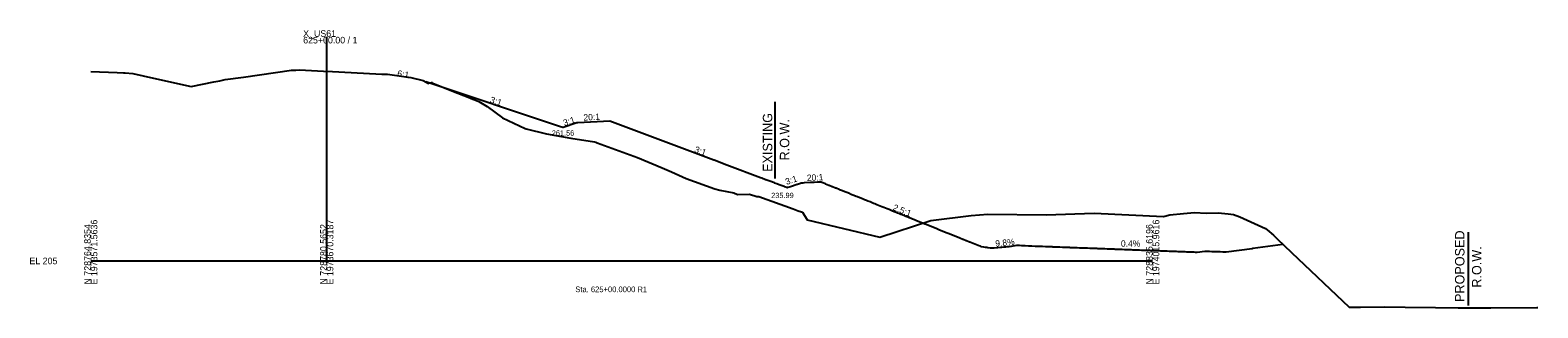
# Model space of a CAD drawing. Extents: x -26 to 630, y -39 to 9098.
# Drawn here: x -26 to 613, y 2480 to 2598 of the extents above; entities that cross this region are included whole.
import ezdxf

# ---------------------------------------------------------------- set-up
doc = ezdxf.new("R2010")
doc.units = 0
for name, color, linetype in [('CONST_DCH', 7, 'Continuous'), ('Default', 7, 'Continuous'), ('Draft_XS_Grid', 7, 'Continuous'), ('Draft_XS_Text', 7, 'Continuous'), ('DTM CONTOURS_MAJOR', 7, 'Continuous'), ('DTM_X_GROUND', 7, 'Continuous'), ('X_DTM_CONTOURS_MAJOR', 7, 'Continuous'), ('XS_CELL', 7, 'Continuous'), ('XS_P_GROUND', 7, 'Continuous'), ('XS_P_ROW', 7, 'Continuous'), ('XS_P_TX_DCH', 7, 'Continuous'), ('XS_P_TX_FS_BS', 7, 'Continuous'), ('XS_X_ROW', 7, 'Continuous')]:
    doc.layers.add(name, color=color, linetype=linetype)

msp = doc.modelspace()

# ---------------------------------------------------------------- linework, layer by layer
at = {"layer": 'DTM_X_GROUND'}
msp.add_lwpolyline([(0, 2580.3), (11.19, 2579.9), (13.9, 2579.81), (14.57, 2579.76), (17.78, 2579.5), (26.51, 2577.53), (42.52, 2573.93), (52.18, 2575.92), (54.64, 2576.42), (56.93, 2576.9), (64.73, 2577.95), (85.12, 2580.85), (86.96, 2580.91), (88.47, 2580.96), (98.67, 2580.48), (102.39, 2580.31), (120.83, 2579.29), (123.37, 2579.15), (123.68, 2579.15), (125.72, 2579.15), (135.68, 2577.7), (140.89, 2576.56), (143.07, 2575.21), (143.58, 2575.49), (144.39, 2575.7), (144.61, 2575.62), (144.93, 2575.39), (145.72, 2575.05), (153.72, 2571.82), (158.12, 2570.1), (159.89, 2569.41), (161.92, 2568.62), (162.07, 2568.56), (164.42, 2567.52), (167.94, 2565.51), (174.48, 2560.69), (184.09, 2556.1), (184.45, 2555.96), (193.07, 2553.95), (203.5, 2552.1), (213.51, 2550.53), (214.08, 2550.34), (214.59, 2550.13), (231.73, 2543.82), (242.14, 2539.43), (246.11, 2537.81), (252.29, 2534.95), (264.47, 2530.56), (266.54, 2530), (272.46, 2528.82), (274.03, 2528.18), (279.09, 2528.33), (282.28, 2527.36), (282.33, 2527.36), (282.49, 2527.33), (282.66, 2527.31), (283.11, 2527.25), (297.66, 2522.07), (299.83, 2521.3), (301.22, 2520.81), (301.6, 2520.68), (303.55, 2517.41), (334.34, 2510.01), (355.93, 2517.07), (373.03, 2519.2), (380.1, 2519.82), (404.84, 2519.51), (425.28, 2520.24), (454.58, 2518.87), (457.31, 2519.61), (463.03, 2520.17), (467.75, 2520.46), (472.69, 2520.2), (477.83, 2520.32), (481.97, 2519.94), (484.21, 2519.67), (486.9, 2518.73), (497.76, 2513.69), (498.58, 2513.16), (501.24, 2510.99), (502.78, 2509.41), (508.86, 2503.62), (533.24, 2480.42), (538.12, 2480.42), (548.11, 2480.5), (557.01, 2480.4), (569.85, 2480.26), (579.4, 2480.15), (593.33, 2480.1), (612.75, 2480.22), (613.23, 2480.19)], dxfattribs=at)
at = {"layer": 'XS_CELL'}
for p, q in [((100, 2500), (100, 2595)), ((0, 2500), (100, 2500)), ((100, 2500), (450, 2500))]:
    msp.add_line(p, q, dxfattribs=at)
at = {"layer": 'XS_P_GROUND'}
for points in [[(309.68, 2533.42), (308.78, 2533.38), (308.07, 2533.34), (308, 2533.34), (306.61, 2533.27), (306.56, 2533.26), (305.14, 2533.19), (305.07, 2533.19), (302.36, 2533.05), (302.32, 2533.05), (301.75, 2533.02), (301.15, 2532.99), (300.92, 2532.91), (300.78, 2532.87), (299.47, 2532.43), (299.36, 2532.4), (296.56, 2531.46), (296.52, 2531.45), (295.41, 2531.08), (295.15, 2530.99), (295.11, 2531.01), (294.96, 2531.07), (293.96, 2531.44), (293.85, 2531.49), (291.77, 2532.27), (291.73, 2532.28), (290.73, 2532.66), (290.7, 2532.67), (289.73, 2533.03), (289.68, 2533.05), (287.82, 2533.75), (287.8, 2533.76), (286.92, 2534.09), (286.89, 2534.1), (286.04, 2534.42), (285.99, 2534.44), (284.36, 2535.05), (283.77, 2535.27), (269.48, 2540.65), (264.13, 2542.66), (263.99, 2542.72), (221.04, 2558.87), (220, 2559.26), (206.35, 2558.58), (206, 2558.56), (200.15, 2556.61), (200, 2556.56), (198.57, 2557.03), (142, 2575.89)], [(309.68, 2533.42), (309.84, 2533.36), (309.84, 2533.36), (311.29, 2532.77), (311.35, 2532.75), (312.75, 2532.18), (312.85, 2532.14), (314.21, 2531.6), (314.36, 2531.53), (315.66, 2531.01), (315.86, 2530.93), (317.12, 2530.42), (317.36, 2530.32), (318.57, 2529.83), (318.86, 2529.72), (320.03, 2529.25), (320.36, 2529.11), (321.48, 2528.66), (321.86, 2528.51), (322.94, 2528.07), (323.35, 2527.9), (324.4, 2527.48), (324.85, 2527.3), (325.85, 2526.9), (326.34, 2526.7), (327.31, 2526.31), (327.84, 2526.1), (328.76, 2525.72), (329.33, 2525.49), (330.22, 2525.14), (330.82, 2524.89), (331.67, 2524.55), (332.32, 2524.29), (333.13, 2523.96), (333.81, 2523.69), (334.59, 2523.37), (335.3, 2523.09), (336.04, 2522.79), (336.79, 2522.49), (337.5, 2522.2), (338.27, 2521.88), (338.95, 2521.61), (339.76, 2521.28), (340.41, 2521.02), (341.25, 2520.68), (341.86, 2520.44), (342.45, 2520.2), (343.32, 2519.85), (343.89, 2519.62), (344.77, 2519.26), (345.33, 2519.04), (346.23, 2518.67), (346.77, 2518.46), (347.69, 2518.09), (348.21, 2517.87), (349.14, 2517.5), (349.65, 2517.29), (350.6, 2516.91), (351.09, 2516.71), (352.05, 2516.33), (352.53, 2516.13), (353.51, 2515.74), (353.96, 2515.56), (354.96, 2515.15), (355.4, 2514.98), (356.42, 2514.56), (356.83, 2514.4), (357.88, 2513.98), (358.27, 2513.82), (359.33, 2513.39), (359.7, 2513.24), (360.79, 2512.8), (361.13, 2512.66), (362.24, 2512.21), (362.56, 2512.08), (363.7, 2511.63), (363.99, 2511.51), (365.15, 2511.04), (365.42, 2510.93), (366.61, 2510.45), (366.85, 2510.35), (368.07, 2509.86), (368.28, 2509.78), (369.52, 2509.28), (369.7, 2509.2), (370.98, 2508.69), (371.13, 2508.63), (372.43, 2508.1), (372.55, 2508.05), (373.89, 2507.52), (373.97, 2507.48), (375.34, 2506.93), (375.39, 2506.91), (376.8, 2506.34), (376.81, 2506.34), (377.21, 2506.17), (378.26, 2506.01), (379.06, 2505.88), (379.71, 2505.77), (380.14, 2505.7), (381.17, 2505.54), (381.34, 2505.51)], [(381.34, 2505.51), (382.62, 2505.61), (382.79, 2505.62), (384.08, 2505.73), (384.44, 2505.76), (385.53, 2505.85), (386.09, 2505.89), (386.99, 2505.96), (387.74, 2506.03), (388.45, 2506.08), (388.9, 2506.12), (389.18, 2506.14), (389.99, 2506.26), (390.24, 2506.29), (392.4, 2506.62), (392.58, 2506.64), (393.11, 2506.72), (393.15, 2506.73), (393.16, 2506.73), (393.56, 2506.7), (394.42, 2506.53), (394.44, 2506.53), (395.87, 2506.48), (395.91, 2506.48), (397.32, 2506.42), (397.38, 2506.42), (398.76, 2506.37), (398.85, 2506.37), (400.21, 2506.32), (400.32, 2506.31), (401.65, 2506.26), (401.79, 2506.26), (403.1, 2506.21), (403.26, 2506.2), (404.55, 2506.15), (404.74, 2506.15), (405.99, 2506.1), (406.21, 2506.09), (407.44, 2506.05), (407.68, 2506.04), (408.89, 2505.99), (409.15, 2505.98), (410.34, 2505.94), (410.62, 2505.93), (411.79, 2505.88), (412.09, 2505.87), (413.24, 2505.83), (413.56, 2505.82), (414.7, 2505.77), (415.03, 2505.76), (416.15, 2505.72), (416.5, 2505.71), (417.61, 2505.67), (417.97, 2505.65), (419.06, 2505.61), (419.44, 2505.6), (420.52, 2505.56), (420.91, 2505.54), (421.97, 2505.5), (422.39, 2505.49), (423.43, 2505.45), (423.86, 2505.43), (424.89, 2505.39), (425.33, 2505.38), (426.34, 2505.34), (426.8, 2505.32), (427.8, 2505.28), (428.27, 2505.27), (429.26, 2505.23), (429.74, 2505.21), (430.72, 2505.18), (431.21, 2505.16), (432.18, 2505.12), (432.68, 2505.1), (433.64, 2505.07), (434.15, 2505.05), (435.1, 2505.01), (435.62, 2504.99), (436.56, 2504.96), (437.09, 2504.94), (438.02, 2504.9), (438.56, 2504.88), (439.48, 2504.85), (440.04, 2504.83), (440.96, 2504.79), (441.51, 2504.77), (442.42, 2504.74), (442.98, 2504.72), (443.87, 2504.68), (444.45, 2504.66), (445.33, 2504.63), (445.92, 2504.61), (446.52, 2504.59), (447.39, 2504.55), (448.01, 2504.53), (448.86, 2504.5), (449.5, 2504.47), (450.33, 2504.44), (450.99, 2504.42), (451.8, 2504.39), (452.48, 2504.36), (453.27, 2504.33), (453.97, 2504.31), (454.74, 2504.28), (455.46, 2504.25), (456.21, 2504.22), (456.94, 2504.2), (457.68, 2504.17), (458.43, 2504.14), (459.16, 2504.11), (459.92, 2504.08), (460.63, 2504.06), (461.42, 2504.03), (462.1, 2504), (462.91, 2503.97), (463.57, 2503.95), (464.4, 2503.92), (465.04, 2503.89), (465.89, 2503.86), (466.51, 2503.84), (467.38, 2503.81), (467.98, 2503.78), (468.51, 2503.76), (468.86, 2503.75), (472.15, 2504.1), (472.57, 2504.12), (473.56, 2504.09), (474.09, 2504.07), (475.1, 2504.04), (475.61, 2504.03), (476.64, 2504), (477.13, 2503.99), (478.19, 2503.96), (478.65, 2503.94), (479.73, 2503.91), (480.17, 2503.9), (480.85, 2503.88), (481.12, 2503.87), (492.15, 2505.31), (492.43, 2505.35), (505.14, 2507.11)]]:
    msp.add_lwpolyline(points, dxfattribs=at)
at = {"layer": 'XS_P_ROW'}
msp.add_line((583.73, 2512.13), (583.73, 2481.12), dxfattribs=at)
at = {"layer": 'XS_X_ROW'}
msp.add_line((290, 2535), (290, 2567.48), dxfattribs=at)

# ---------------------------------------------------------------- texts
at = {"layer": 'CONST_DCH'}
msp.add_text('X', height=0.001, dxfattribs=at).set_placement((393.56, 2506.7))
at = {"layer": 'Default'}
for p in [(199.96, 2556.5), (199.96, 2556.5), (295.12, 2530.93), (356.5, 2517.08)]:
    msp.add_text('X', height=0.12, dxfattribs=at).set_placement(p)
at = {"layer": 'Draft_XS_Grid'}
msp.add_text('-', height=0.0001, dxfattribs=at).set_placement((0, 2500))
at = {"layer": 'Draft_XS_Text'}
msp.add_text('Sta. 625+00.0000 R1', height=2.4, dxfattribs=at).set_placement((205.34, 2486.75))
at = {"layer": 'DTM CONTOURS_MAJOR'}
msp.add_text('X', height=0.001, dxfattribs=at).set_placement((200, 2556.56))
at = {"layer": 'X_DTM_CONTOURS_MAJOR'}
for height, p in [(0.12, (121.96, 2579.17)), (0.12, (141.96, 2575.83)), (0.12, (141.96, 2575.83)), (0.001, (142, 2575.89)), (0.12, (205.96, 2558.5)), (0.12, (205.96, 2558.5)), (0.001, (206, 2558.56)), (0.12, (219.96, 2559.2)), (0.12, (219.96, 2559.2)), (0.001, (220, 2559.26)), (0.12, (280.05, 2533.5)), (0.12, (301.12, 2532.93)), (0.12, (315.12, 2533.63))]:
    msp.add_text('X', height=height, dxfattribs=at).set_placement(p)
at = {"layer": 'XS_CELL'}
for s, p in [('X_US61', (90, 2595)), ('625+00.00 / 1', (90, 2592.2)), ('EL 205', (-26, 2498.6))]:
    msp.add_text(s, height=2.8, dxfattribs=at).set_placement(p)
for s, p in [('N 728764.8354', (0, 2490)), ('E 1973571.5636', (2.8, 2490)), ('N 728780.5652', (100, 2490)), ('E 1973670.3187', (102.8, 2490)), ('N 728835.6196', (450, 2490)), ('E 1974015.9616', (452.8, 2490))]:
    msp.add_text(s, height=2.8, rotation=90, dxfattribs=at).set_placement(p)
at = {"layer": 'XS_P_ROW'}
for s, p in [('EXISTING', (288.8, 2537.76)), ('R.O.W.', (296, 2542.6)), ('PROPOSED', (582.13, 2482.6)), ('R.O.W.', (589.33, 2488.67))]:
    msp.add_text(s, height=4, rotation=90, dxfattribs=at).set_placement(p)
at = {"layer": 'XS_P_TX_DCH'}
for s, p in [('261.56', (195.37, 2553.11)), ('235.99', (288.36, 2526.64))]:
    msp.add_text(s, height=2.25, dxfattribs=at).set_placement(p)
at = {"layer": 'XS_P_TX_FS_BS'}
for s, rotation, p in [('6:1', 350.53768, (129.72, 2578.24)), ('3:1', 341.56505, (168.92, 2567.24)), ('20:1', 2.86247, (208.83, 2559.47)), ('3:1', 18.43495, (200.73, 2557.12)), ('3:1', 339.38947, (255.53, 2546.22)), ('20:1', 2.86247, (303.51, 2533.86)), ('3:1', 18.43495, (294.88, 2532.19)), ('2.5:1', 338.02739, (339.64, 2521.66)), ('9.8%', 5.59374, (383.42, 2506.01)), ('0.4%', 0.20945, (436.54, 2506.02))]:
    msp.add_text(s, height=2.7, rotation=rotation, dxfattribs=at).set_placement(p)

doc.saveas('drawing.dxf')
